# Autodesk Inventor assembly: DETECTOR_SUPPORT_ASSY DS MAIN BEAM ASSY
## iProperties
Shininess: 64.0
Length Units: 11272
Angle Units: 11279
Time Units: 11290
Mass Units: 11286
Length Display Precision: 3
Angle Display Precision: 2
Compacted: True
Part Number: DETECTOR_SUPPORT_ASSY DS MAIN BEAM ASSY
Document SubType Name: Assembly
Created: 2004-08
Designer: John Blackburn
Manufacturer: Standard
Standards Organization: Custom
Density: 0.0
Volumn: 0.0
Area: 0.0
PropertySet Name: Model Information
Control State: 0
Master: False
Checked Out: False
Author: John Blackburn
